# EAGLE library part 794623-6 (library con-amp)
MICRO MATE N LOK Dual Row, grid 1.5 mm Source: http://catalog.tycoelectronics.com .. ENG_CD_794623_F.pdf
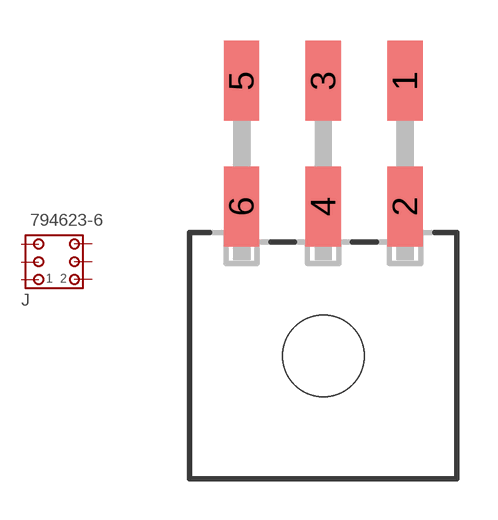
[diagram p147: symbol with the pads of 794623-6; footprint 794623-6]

Designator prefix J

## 794623-6 (MF: TYCO ELECTRONICS; MPN: 794623-6; OC_FARNELL: unknown; OC_NEWARK: 19H3720)  [794623-6]
1  1  pas
2  2  pas
3  3  pas
4  4  pas
5  5  pas
6  6  pas

## Footprint 794623-6 (pad centres in mm)
MICRO MATE N LOK Dual Row, grid 1.5 mm Source: http://catalog.tycoelectronics.com .. ENG_CD_794623_F.pdf
smd 1.3 x 2.92: 1 3,10.1; 2 3,5.48; 3 0,10.1; 4 0,5.48; 5 -3,10.1; 6 -3,5.48
hole 3 at 0,0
